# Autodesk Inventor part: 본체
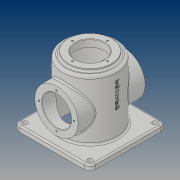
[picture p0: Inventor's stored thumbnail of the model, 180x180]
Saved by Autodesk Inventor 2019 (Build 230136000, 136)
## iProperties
Created: 2019-03
Part Number: 본체
Material: 일반
Document SubType Name: Modeling
Designer: PC312-19
Density: 1 g/cm^3
Appearance: 기본값
Author: PC312-19
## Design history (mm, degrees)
sketch "스케치1"
  geometry: C1 r 50 at (0, 0); 1 further point
  constraints: 1 centre point, 1 coincident
  dimensions: "d0" = 100 diameter of C1
extrude "돌출1" new body sketch "스케치1" stored distance "d1" = 120; taper "d2" = 0 deg
sketch "스케치2"
  geometry: C1 r 45 at (0, 0); 1 further point
  constraints: 1 centre point, 1 coincident
  dimensions: "d3" = 90 diameter of C1
extrude "돌출2" cut sketch "스케치2" distance "d4" = 112; taper "d5" = 0 deg
sketch "스케치3"
  geometry: C1 r 40 at (0, 0); 1 further point
  constraints: 1 centre point, 1 coincident
  dimensions: "d6" = 80 diameter of C1
extrude "돌출3" join sketch "스케치3" distance "d7" = 5; taper "d8" = 0 deg
sketch "스케치4"
  geometry: C1 r 27 at (0, 0); 1 further point
  constraints: 1 centre point, 1 coincident
  dimensions: "d9" = 54 diameter of C1
extrude "돌출4" cut sketch "스케치4" distance "d10" = 13; taper "d11" = 0 deg
node "작업 평면1"
sketch "스케치6"
  geometry: C1 r 40 at (0, 0); 1 further point
  constraints: 1 centre point, 1 coincident
  dimensions: "d13" = 80 diameter of C1
extrude "돌출5" join sketch "스케치6" stored distance "d14" = 13; taper "d15" = 0 deg
sketch "스케치7"
  geometry: 2 further points
  constraints: 1 vertical alignment
  dimensions: "d16" = 32.5 distance of point (0, 0) point (0, 32.5)
hole "구멍1" sketch "스케치7" at (0, 32.5) diameter "d17" = 3.242; stored, may be unused: countersink angle "d21" = 90 deg, drill point angle "d23" = 118 deg; dims "d18" = 8, "d19" = 4, "d20" = 2, "d22" = 10
sketch "스케치8"
  geometry: C1 r 27 at (0, 0); 1 further point
  constraints: 1 centre point, 1 coincident
  dimensions: "d27" = 54 diameter of C1
extrude "돌출6" cut sketch "스케치8" extent not by distance; stored distance "d28" = 13; taper "d29" = 0 deg
sketch "스케치9"
  geometry: L1 (70, 70)-(-70, 70); L2 (-70, 70)-(-70, -70); L3 (-70, -70)-(70, -70); L4 (70, -70)-(70, 70); L5 (70, 70)-(-70, -70); L6 (-70, 70)-(70, -70); C1 r 50 at (0, 0) reference; C2 r 45 at (0, 0) reference; 1 further point
  constraints: 12 end point, 2 midpoint, 2 parallel, 1 horizontal, 1 perpendicular
  dimensions: "d30" = 140 distance of L3.end L2.end; "d31" = 140 distance of L2.end L1.end
extrude "돌출7" join sketch "스케치9" distance "d32" = 10; taper "d33" = 0 deg
fillet "모깎기1" dims "d34" = 10
sketch "스케치10"
  geometry: C1 r 4.5 at (60, -60); C2 r 4.5 at (-60, -60); C3 r 4.5 at (-60, 60); C4 r 4.5 at (60, 60); 13 further points
  constraints: 4 centre point, 4 coincident, 4 other
  dimensions: "d35" = 9 diameter of C1; "d36" = 9 diameter of C2; "d37" = 9 diameter of C3; "d38" = 9 diameter of C4
extrude "돌출8" cut sketch "스케치10" extent not by distance; stored distance "d39" = 10; taper "d40" = 0 deg
node "작업 평면2"
sketch "스케치11"
  geometry: 6 further points; 1 other entity
  constraints: 1 horizontal alignment, 2 other
  dimensions: "d42" = 70 dimension on point (20, 0)
feature "엠보싱1" sketch "스케치11" dims "d12" = 62, "d43" = 0.5, "d44" = 0
fillet "모깎기2" dims "d45" = 3
fillet "모깎기3" dims "d46" = 5
fillet "모깎기4" dims "d47" = 3
chamfer "모따기1" distance "d48" = 1; stored, may be unused: second distance "d49" = 2, angle "d50" = 45 deg
sketch "스케치12"
  geometry: 2 further points
  constraints: 1 vertical alignment
  dimensions: "d52" = 32.5 distance of point (0, 0) point (0, 32.5)
hole "구멍2" sketch "스케치12" at (0, 32.5) diameter "d53" = 3.242; stored, may be unused: countersink angle "d57" = 90 deg, drill point angle "d59" = 118 deg; dims "d54" = 8, "d55" = 4, "d56" = 2, "d58" = 10
fillet "모깎기6" dims "d63" = 3
fillet "모깎기7" dims "d64" = 3
node "솔리드1"
pattern_circular "원형 패턴1" dims angle "d25" = 360 deg
mirror "미러1"
pattern_circular "원형 패턴2" dims angle "d61" = 360 deg
other parameters: "d41" = 95.5
